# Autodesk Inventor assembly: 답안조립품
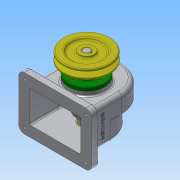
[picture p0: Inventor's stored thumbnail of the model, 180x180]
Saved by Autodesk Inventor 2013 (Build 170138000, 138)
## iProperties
Created: 2017-11
Part Number: 답안조립품
Document SubType Name: Assembly
Designer: Administrator
Author: Administrator
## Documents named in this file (14)
- C:\Users\Administrator\Desktop\471108V1019\답안조립품.iam
- C:\Users\Administrator\Desktop\471108V1019\본체.ipt
- C:\Users\Administrator\Desktop\471108V1019\V-벨트풀리.ipt
- C:\Users\Administrator\Desktop\471108V1019\뒤커버.ipt
- C:\Users\Administrator\Desktop\471108V1019\멈춤나사 - M4 x 10.ipt
- 멈춤나사 - M4 x 10.ipt
- C:\Users\Administrator\Desktop\471108V1019\베어링 6002.ipt
- C:\Users\Administrator\Desktop\471108V1019\볼트 M3 x 8.ipt
- C:\Users\Administrator\Desktop\471108V1019\스퍼기어.ipt
- C:\Users\Administrator\Desktop\471108V1019\앞커버.ipt
- C:\Users\Administrator\Desktop\471108V1019\오일 실 15 30 7.ipt
- C:\Users\Administrator\Desktop\471108V1019\축.ipt
- C:\Users\Administrator\Desktop\471108V1019\키 - 5 x 5 x 18.ipt
- C:\Users\Administrator\Desktop\471108V1019\키 - 6 x 6 x 22.ipt
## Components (1 placed, 1 different names)
1. V-벨트풀리:1
